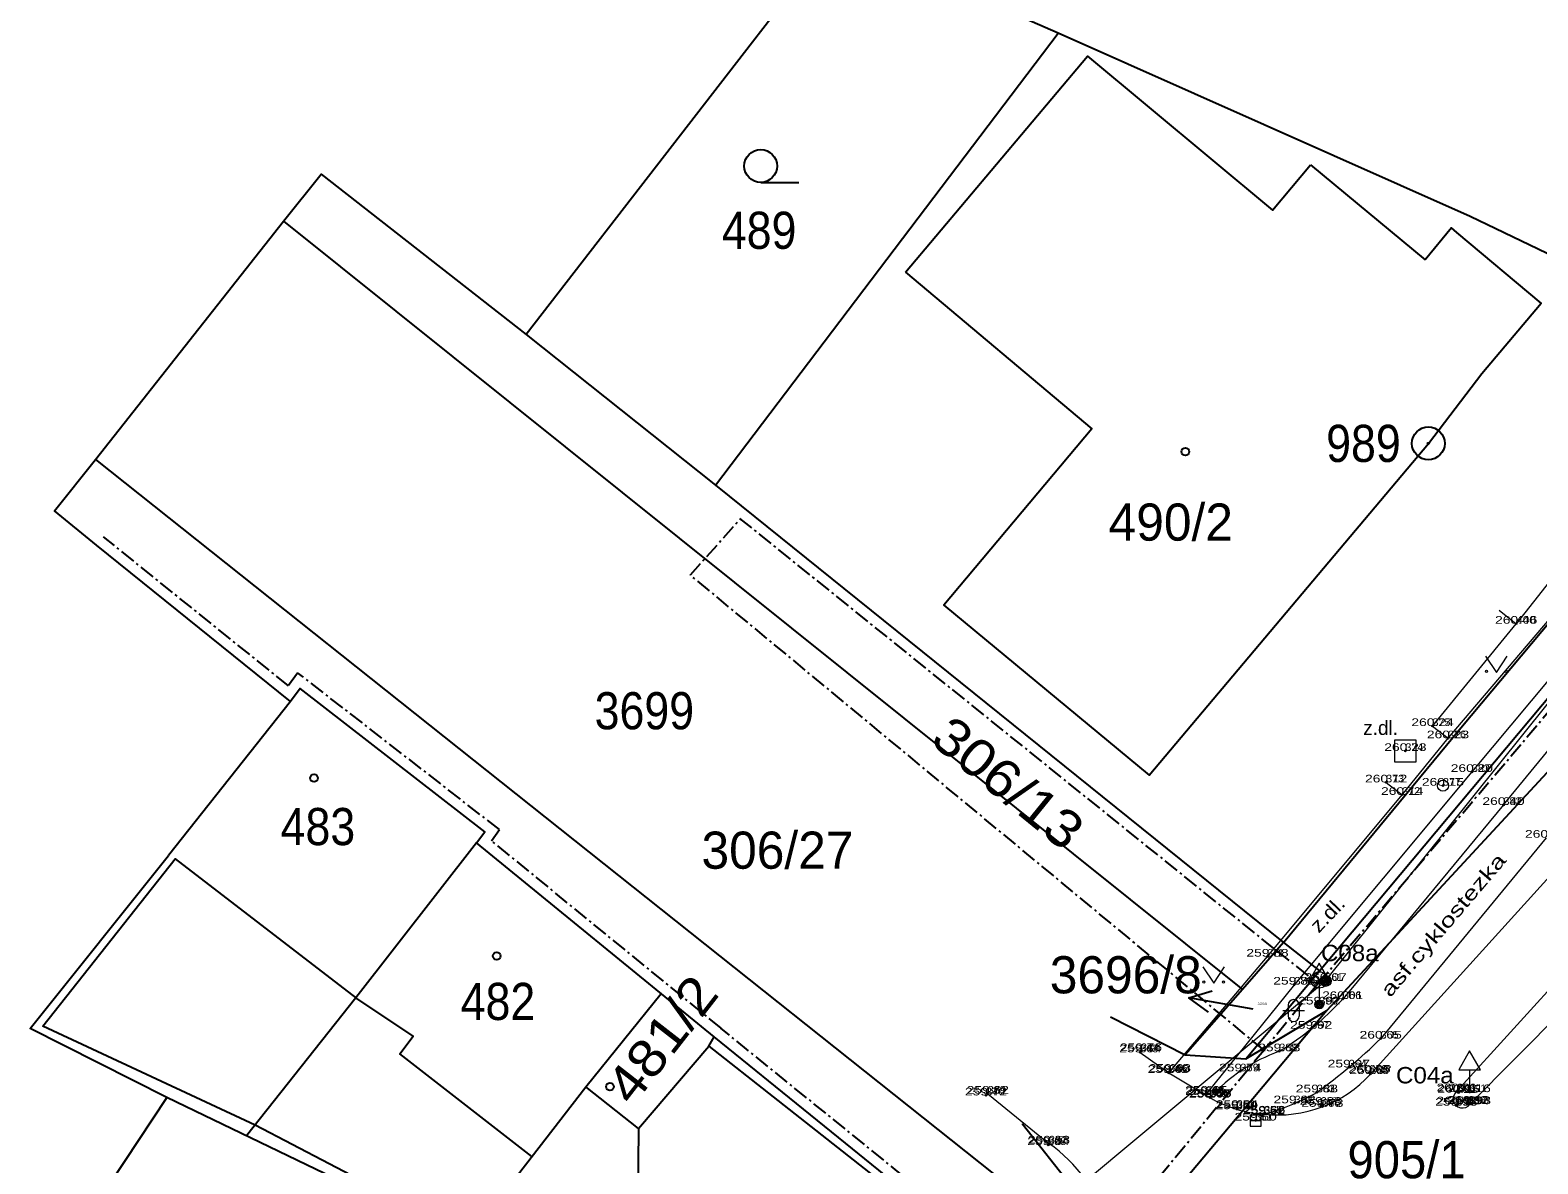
# Model space of a CAD drawing. Extents: x -568530 to -568223, y -1154101 to -1153740.
# Drawn here: x -568529.8 to -568460.8, y -1153988.4 to -1153936.5 of the extents above; entities that cross this region are included whole.
import ezdxf
from ezdxf.enums import TextEntityAlignment as Align

# ---------------------------------------------------------------- set-up
doc = ezdxf.new("R2010")
doc.units = 0
doc.header["$LTSCALE"] = 0.14
doc.header["$PDMODE"] = 32
doc.header["$PDSIZE"] = 0.07
doc.linetypes.add('DOT_DASHED', pattern=[7.7, 5, -1.2, 0.3, -1.2])
for name, color, linetype, lineweight in [('1', 7, 'Continuous', 25), ('10', 7, 'Continuous', 13), ('11', 7, 'Continuous', 13), ('12', 7, 'Continuous', 13), ('17', 7, 'Continuous', 13), ('25', 7, 'Continuous', 13), ('26', 7, 'Continuous', 13), ('27', 7, 'Continuous', 13), ('28', 7, 'Continuous', 13), ('33', 7, 'Continuous', 13), ('34', 7, 'Continuous', 13), ('36', 7, 'Continuous', 13), ('4', 7, 'Continuous', 25), ('42', 7, 'Continuous', 13), ('51', 7, 'Continuous', 13), ('6', 7, 'DOT_DASHED', 25), ('7', 7, 'Continuous', 13)]:
    doc.layers.add(name, color=color, linetype=linetype, lineweight=lineweight)
for name, color, linetype in [('13', 7, 'Continuous'), ('18', 7, 'Continuous'), ('19', 7, 'Continuous'), ('20', 7, 'Continuous'), ('40', 7, 'Continuous')]:
    doc.layers.add(name, color=color, linetype=linetype)

msp = doc.modelspace()

# ---------------------------------------------------------------- linework, layer by layer
at = {"layer": '1'}
for p, q in [((-568463.93, -1153945.07), (-568482.79, -1153936.68)), ((-568471.25, -1153942.71), (-568466, -1153947.05)), ((-568450.23, -1153951.69), (-568463.93, -1153945.07)), ((-568517.91, -1153967.26), (-568523.5, -1153974.31)), ((-568472.48, -1153978.28), (-568470.83, -1153979.58))]:
    msp.add_line(p, q, dxfattribs=at)
for points in [[(-568474.2, -1153983.6), (-568452.46, -1153957.65), (-568449.01, -1153953.16), (-568441.85, -1153945.56), (-568434.01, -1153937.23), (-568430.2, -1153935.69), (-568428.09, -1153933.47), (-568426.88, -1153931.62), (-568414.57, -1153911.32), (-568413.31, -1153909.52)], [(-568421.22, -1153939.56), (-568428.14, -1153935.17), (-568430.26, -1153937.4), (-568443.63, -1153952.29), (-568447.7, -1153956.78), (-568470.49, -1153981.39)], [(-568489.78, -1153947.62), (-568481.45, -1153937.73), (-568472.98, -1153944.78), (-568471.25, -1153942.71)], [(-568526.84, -1153956.18), (-568518.24, -1153945.29), (-568516.51, -1153943.13), (-568507.14, -1153950.47)], [(-568465.85, -1153955.45), (-568463.4, -1153952.25), (-568460.68, -1153949.03), (-568464.54, -1153945.8), (-568464.79, -1153945.59), (-568466, -1153947.05)], [(-568489.78, -1153947.62), (-568481.25, -1153954.78), (-568488.02, -1153962.85), (-568478.62, -1153970.63), (-568465.85, -1153955.45)], [(-568498.47, -1153957.36), (-568472.48, -1153978.28), (-568467.49, -1153972.24), (-568464.36, -1153968.47), (-568450.95, -1153952.46)], [(-568483.3, -1153990.8), (-568485.31, -1153993.31), (-568498.53, -1153982.6), (-568509.4, -1153973.73), (-568509.03, -1153973.22), (-568517.48, -1153966.66), (-568517.91, -1153967.26), (-568526.79, -1153960.11), (-568528.72, -1153958.54), (-568526.84, -1153956.18)], [(-568509.4, -1153973.73), (-568514.92, -1153980.82), (-568519.93, -1153987.13)], [(-568523.58, -1153985.37), (-568529.83, -1153982.22), (-568523.5, -1153974.31)], [(-568472.48, -1153978.28), (-568474.36, -1153980.44), (-568476.98, -1153983.42), (-568474.2, -1153983.6), (-568470.49, -1153981.39)], [(-568501.99, -1153986.8), (-568504.41, -1153984.88), (-568500.96, -1153980.62)], [(-568470.49, -1153981.39), (-568474.36, -1153986), (-568480.23, -1153992.99), (-568483.12, -1153996.42), (-568489.9, -1154005.63), (-568508.72, -1154028.73)], [(-568501.99, -1153986.8), (-568498.78, -1153983.02), (-568498.53, -1153982.6)], [(-568502.03, -1153990.93), (-568508.67, -1153990.41), (-568504.41, -1153984.88)], [(-568508.67, -1153990.41), (-568510.29, -1153992.32), (-568515.06, -1153989.47), (-568523.58, -1153985.37), (-568528.1, -1153992.22), (-568521.58, -1153995.13), (-568500.56, -1154012.05), (-568494.94, -1154005.21), (-568491.05, -1154000.52)]]:
    msp.add_lwpolyline(points, dxfattribs=at)
msp.add_lwpolyline([(-568498.47, -1153957.36), (-568482.79, -1153936.68), (-568493.01, -1153932.21), (-568507.14, -1153950.47)], close=True, dxfattribs=at)
at = {"layer": '10'}
for p, q in [((-568468.5, -1153984.3), (-568459.56, -1153974.44)), ((-568464.54, -1153985.09), (-568457.22, -1153977.01)), ((-568486.01, -1153985.2), (-568483.21, -1153987.48))]:
    msp.add_line(p, q, dxfattribs=at)
for points in [[(-568463.95, -1153985.68), (-568459.72, -1153981.43), (-568456.47, -1153977.68)], [(-568479.03, -1153983.31), (-568477.73, -1153984.25), (-568476.04, -1153985.26), (-568475.84, -1153985.38)]]:
    msp.add_lwpolyline(points, dxfattribs=at)
for centre, radius, start, end in [((-568472.7383, -1153980.4472), 5.7278, 263.66789, 317.72758), ((-568472.9663, -1153980.4342), 5.7201, 239.84169, 265.95285), ((-568464.292, -1153985.432), 0.4224, 125.95584, 324.04416), ((-568487.1888, -1153993.1519), 6.9283, 16.6224, 54.95079)]:
    msp.add_arc(centre, radius, start, end, dxfattribs=at)
at = {"layer": '11'}
for p, q in [((-568465.66, -1153968.38), (-568461.83, -1153963.7)), ((-568465.66, -1153968.38), (-568464.95, -1153968.94)), ((-568463.86, -1153970.48), (-568471.98, -1153980.21)), ((-568467.78, -1153970.96), (-568467.05, -1153971.53)), ((-568462.41, -1153971.99), (-568469.77, -1153980.87)), ((-568460.46, -1153973.49), (-568468.03, -1153982.68)), ((-568477.73, -1153984.25), (-568473.21, -1153978.93)), ((-568471.98, -1153980.21), (-568476.04, -1153985.26))]:
    msp.add_line(p, q, dxfattribs=at)
for points in [[(-568442.59, -1153945.91), (-568443.65, -1153947.05), (-568450.12, -1153954.09), (-568450.55, -1153954.6), (-568457.5, -1153962.87), (-568463.86, -1153970.48)], [(-568462.41, -1153971.99), (-568455.94, -1153964.12), (-568449.09, -1153955.83), (-568442.48, -1153947.86)], [(-568464.95, -1153968.94), (-568458.91, -1153961.84), (-568451.46, -1153952.92)], [(-568473.21, -1153978.93), (-568467.05, -1153971.53), (-568464.95, -1153968.94)]]:
    msp.add_lwpolyline(points, dxfattribs=at)
for centre, radius, start, end in [((-568479.5527, -1153971.9543), 13.236, 301.33199, 317.65447), ((-568486.5097, -1153963.7078), 26.4848, 305.97945, 314.24653), ((-568469.9419, -1153990.7693), 7.9896, 109.96597, 137.58085), ((-568476.5758, -1153974.9538), 11.6365, 285.99146, 298.91164)]:
    msp.add_arc(centre, radius, start, end, dxfattribs=at)
for p in [(-568461.83, -1153963.7), (-568465.66, -1153968.38), (-568464.95, -1153968.94), (-568466.9, -1153969.52), (-568463.86, -1153970.48), (-568467.78, -1153970.96), (-568465.18, -1153971.11), (-568467.05, -1153971.53), (-568462.41, -1153971.99), (-568473.21, -1153978.93), (-568470.55, -1153980.04), (-568471.98, -1153980.21), (-568470.84, -1153981.12), (-568469.77, -1153980.87), (-568471.21, -1153982.23), (-568468.03, -1153982.68), (-568479.03, -1153983.31), (-568479, -1153983.25), (-568472.67, -1153983.26), (-568477.73, -1153984.25), (-568477.68, -1153984.2), (-568474.46, -1153984.18), (-568469.49, -1153984), (-568468.54, -1153984.24), (-568468.5, -1153984.3), (-568486.09, -1153985.28), (-568486.01, -1153985.2), (-568476.04, -1153985.26), (-568476.01, -1153985.2), (-568475.84, -1153985.38), (-568475.82, -1153985.35), (-568471.97, -1153985.64), (-568470.95, -1153985.14), (-568464.54, -1153985.09), (-568464.47, -1153985.15), (-568464.02, -1153985.66), (-568463.96, -1153985.13), (-568474.62, -1153985.91), (-568474.61, -1153985.85), (-568473.37, -1153986.14), (-568473.36, -1153986.11), (-568470.77, -1153985.71), (-568470.7, -1153985.8), (-568464.57, -1153985.75), (-568464.51, -1153985.69), (-568463.95, -1153985.68), (-568473.75, -1153986.43), (-568483.24, -1153987.55), (-568483.21, -1153987.48)]:
    msp.add_point(p, dxfattribs=at)
at = {"layer": '25', "lineweight": 25}
for p, q in [((-568496.4, -1153943.51), (-568494.65, -1153943.51)), ((-568473.86, -1153981.34), (-568476.812, -1153980.809))]:
    msp.add_line(p, q, dxfattribs=at)
msp.add_lwpolyline([(-568475.916, -1153981.477), (-568476.812, -1153980.809), (-568475.739, -1153980.494)], dxfattribs=at)
for centre, radius in [((-568496.4, -1153942.76), 0.75), ((-568465.85, -1153955.45), 0.75), ((-568476.97, -1153955.83), 0.175), ((-568465.85, -1153955.45), 0.032), ((-568516.84, -1153970.76), 0.175), ((-568508.48, -1153978.9), 0.175), ((-568503.3, -1153984.88), 0.175)]:
    msp.add_circle(centre, radius, dxfattribs=at)
at = {"layer": '25'}
for radius in [0.25, 0.2, 0.15, 0.1, 0.05]:
    msp.add_circle((-568470.55, -1153980.04), radius, dxfattribs=at)
at = {"layer": '26'}
msp.add_lwpolyline([(-568467.4, -1153970.02), (-568466.4, -1153970.02), (-568466.4, -1153969.02), (-568467.4, -1153969.02)], close=True, dxfattribs=at)
at = {"layer": '27'}
msp.add_line((-568474, -1153986.43), (-568473.5, -1153986.43), dxfattribs=at)
msp.add_lwpolyline([(-568474, -1153986.68), (-568473.5, -1153986.68), (-568473.5, -1153986.18), (-568474, -1153986.18)], close=True, dxfattribs=at)
at = {"layer": '28'}
msp.add_circle((-568465.18, -1153971.11), 0.25, dxfattribs=at)
at = {"layer": '33'}
for p, q in [((-568471.105, -1153980.26), (-568470.575, -1153979.73)), ((-568471.105, -1153979.73), (-568470.575, -1153980.26)), ((-568470.84, -1153980.37), (-568470.84, -1153981.12))]:
    msp.add_line(p, q, dxfattribs=at)
for centre, radius in [((-568470.84, -1153979.995), 0.375), ((-568470.84, -1153981.12), 0.2), ((-568470.84, -1153981.12), 0.1445), ((-568470.84, -1153981.12), 0.0876)]:
    msp.add_circle(centre, radius, dxfattribs=at)
at = {"layer": '34'}
for p, q in [((-568470.84, -1153980.102), (-568470.84, -1153981.12)), ((-568463.96, -1153984.112), (-568463.96, -1153985.13)), ((-568464.21, -1153985.13), (-568463.71, -1153985.13))]:
    msp.add_line(p, q, dxfattribs=at)
for points in [[(-568471.34, -1153980.102), (-568470.34, -1153980.102), (-568470.84, -1153979.236)], [(-568464.46, -1153984.112), (-568463.46, -1153984.112), (-568463.96, -1153983.246)]]:
    msp.add_lwpolyline(points, close=True, dxfattribs=at)
at = {"layer": '36'}
for p, q in [((-568472.514, -1153981.398), (-568471.514, -1153981.398)), ((-568472.264, -1153981.148), (-568472.264, -1153981.648)), ((-568471.764, -1153981.148), (-568471.764, -1153981.648))]:
    msp.add_line(p, q, dxfattribs=at)
for points in [[(-568463.237, -1153965.178), (-568462.737, -1153965.928), (-568462.237, -1153965.178)], [(-568476.172, -1153979.393), (-568475.672, -1153980.143), (-568475.172, -1153979.393)]]:
    msp.add_lwpolyline(points, dxfattribs=at)
for centre in [(-568463.1878, -1153965.8784), (-568462.2884, -1153965.8784), (-568476.1232, -1153980.0934), (-568475.2238, -1153980.0934)]:
    msp.add_circle(centre, 0.05, dxfattribs=at)
for centre, start, end in [((-568472.0136, -1153981.1489), 0, 180), ((-568472.0136, -1153981.6489), 180, 0)]:
    msp.add_arc(centre, 0.25, start, end, dxfattribs=at)
at = {"layer": '4'}
for p, q in [((-568518.24, -1153945.29), (-568474.36, -1153980.44)), ((-568526.84, -1153956.18), (-568483.3, -1153990.8)), ((-568480.4, -1153981.68), (-568476.98, -1153983.42)), ((-568498.78, -1153983.02), (-568485.47, -1153993.49)), ((-568501.99, -1153986.8), (-568502.03, -1153990.93)), ((-568484.44, -1153986.56), (-568482.11, -1153989.53))]:
    msp.add_line(p, q, dxfattribs=at)
for points in [[(-568509.95, -1153991.92), (-568514.46, -1153989.29), (-568519.54, -1153986.64), (-568529.25, -1153982.11), (-568523.19, -1153974.46), (-568514.92, -1153980.82)], [(-568506.87, -1153988.07), (-568512.92, -1153983.38), (-568512.3, -1153982.57), (-568514.92, -1153980.82)]]:
    msp.add_lwpolyline(points, dxfattribs=at)
at = {"layer": '51'}
msp.add_lwpolyline([(-568486.26, -1153993.13), (-568470.55, -1153980.04), (-568452.49, -1153957.53), (-568437.543, -1153968.589)], dxfattribs=at)
at = {"layer": '6'}
for p, q in [((-568470.89, -1153980.16), (-568452.08, -1153957.97)), ((-568499.62, -1153961.47), (-568497.34, -1153958.91)), ((-568497.37, -1153958.88), (-568472.79, -1153978.67)), ((-568518.01, -1153966.54), (-568526.48, -1153959.72)), ((-568473.37, -1153983.21), (-568499.62, -1153961.47)), ((-568517.6, -1153965.96), (-568518.01, -1153966.54)), ((-568508.35, -1153973.12), (-568517.59, -1153965.94)), ((-568508.72, -1153973.63), (-568508.35, -1153973.12)), ((-568498.21, -1153982.21), (-568508.72, -1153973.63)), ((-568472.79, -1153978.67), (-568470.89, -1153980.16)), ((-568482.83, -1153994.68), (-568498.22, -1153982.21))]:
    msp.add_line(p, q, dxfattribs=at)
msp.add_lwpolyline([(-568470.91, -1153980.18), (-568473.37, -1153983.21), (-568482.77, -1153994.61)], dxfattribs=at)
at = {"layer": '7'}
msp.add_line((-568462.615, -1153963.08), (-568461.83, -1153963.7), dxfattribs=at)
msp.add_lwpolyline([(-568450.39, -1153949.74), (-568453.8, -1153950.8), (-568454.03, -1153954.12), (-568459.68, -1153960.98), (-568461.83, -1153963.7)], dxfattribs=at)

# ---------------------------------------------------------------- texts
at = {"layer": '12'}
for s, width, p in [('260.46', 1.35, (-568461.83, -1153963.7)), ('260.24', 1.35, (-568465.66, -1153968.38)), ('260.23', 1.35, (-568464.95, -1153968.94)), ('260.23', 1.35, (-568466.9, -1153969.52)), ('260.20', 1.35, (-568463.8595, -1153970.48)), ('260.12', 1.35, (-568467.78, -1153970.96)), ('260.15', 1.35, (-568465.1805, -1153971.11)), ('260.14', 1.35, (-568467.05, -1153971.53)), ('260.40', 1.35, (-568462.4095, -1153971.99)), ('260.44', 1.35, (-568460.46, -1153973.49)), ('259.88', 1.35, (-568473.21, -1153978.93)), ('259.85', 1.35, (-568471.9805, -1153980.21)), ('260.07', 1.35, (-568470.55, -1153980.04)), ('259.92', 1.35, (-568470.84, -1153981.12)), ('260.01', 1.3, (-568469.77, -1153980.87)), ('259.92', 1.35, (-568471.21, -1153982.23)), ('260.05', 1.35, (-568468.0305, -1153982.68)), ('259.64', 1.35, (-568479.03, -1153983.31)), ('259.76', 1.35, (-568479, -1153983.25)), ('259.83', 1.35, (-568472.67, -1153983.26)), ('259.60', 1.35, (-568477.7295, -1153984.25)), ('259.63', 1.35, (-568477.68, -1153984.2)), ('259.74', 1.35, (-568474.46, -1153984.18)), ('259.97', 1.35, (-568469.49, -1153984)), ('260.05', 1.35, (-568468.5405, -1153984.24)), ('259.87', 1.35, (-568468.5, -1153984.3)), ('259.72', 1.35, (-568486.09, -1153985.28)), ('259.62', 1.35, (-568486.01, -1153985.2)), ('259.65', 1.35, (-568476.0105, -1153985.2)), ('259.61', 1.3, (-568476.04, -1153985.26)), ('259.88', 1.35, (-568470.95, -1153985.14)), ('260.01', 1.3, (-568464.54, -1153985.09)), ('260.15', 1.35, (-568464.4705, -1153985.15)), ('260.16', 1.35, (-568463.96, -1153985.13)), ('259.60', 1.35, (-568475.8395, -1153985.38)), ('259.65', 1.35, (-568475.8205, -1153985.35)), ('259.60', 1.35, (-568474.6195, -1153985.91)), ('259.64', 1.35, (-568474.61, -1153985.85)), ('259.82', 1.35, (-568471.97, -1153985.64)), ('259.88', 1.35, (-568470.77, -1153985.71)), ('259.73', 1.35, (-568470.7, -1153985.8)), ('259.98', 1.35, (-568464.57, -1153985.75)), ('260.12', 1.35, (-568464.51, -1153985.69)), ('260.13', 1.35, (-568464.02, -1153985.66)), ('259.98', 1.35, (-568463.95, -1153985.68)), ('259.60', 1.35, (-568473.7495, -1153986.43)), ('259.62', 1.35, (-568473.37, -1153986.14)), ('259.66', 1.35, (-568473.36, -1153986.11)), ('259.64', 1.35, (-568483.24, -1153987.55)), ('259.53', 1.35, (-568483.21, -1153987.48))]:
    msp.add_text(s, height=0.35, dxfattribs=dict(at, width=width)).set_placement(p, align=Align.CENTER)
at = {"layer": '13'}
for s, width, p in [('400', 1.15, (-568461.83, -1153963.7)), ('375', 1.05, (-568465.66, -1153968.38)), ('376', 1.05, (-568464.95, -1153968.94)), ('374', 1.05, (-568466.9, -1153969.52)), ('383', 1.05, (-568463.86, -1153970.48)), ('373', 1.05, (-568467.78, -1153970.96)), ('377', 1.05, (-568465.18, -1153971.11)), ('372', 1.05, (-568467.05, -1153971.53)), ('382', 1.05, (-568462.41, -1153971.99)), ('371', 0.95, (-568473.21, -1153978.93)), ('370', 1.1, (-568471.98, -1153980.21)), ('360', 1.1, (-568470.84, -1153981.12)), ('366', 1.1, (-568469.77, -1153980.87)), ('367', 1.05, (-568471.21, -1153982.23)), ('365', 1.05, (-568468.03, -1153982.68)), ('343', 1.05, (-568479.03, -1153983.31)), ('344', 1.05, (-568479, -1153983.25)), ('368', 1.05, (-568472.67, -1153983.26)), ('345', 1.05, (-568477.73, -1153984.25)), ('346', 1.05, (-568477.68, -1153984.2)), ('369', 1.1, (-568474.46, -1153984.18)), ('364', 1.05, (-568469.49, -1153984)), ('359', 1.05, (-568468.54, -1153984.24)), ('358', 1.05, (-568468.5, -1153984.3)), ('340', 1.1, (-568486.09, -1153985.28)), ('339', 1.05, (-568486.01, -1153985.2)), ('347', 1.05, (-568476.04, -1153985.26)), ('348', 1.05, (-568476.01, -1153985.2)), ('363', 1.05, (-568470.95, -1153985.14)), ('396', 1.1, (-568464.54, -1153985.09)), ('397', 1.05, (-568464.47, -1153985.15)), ('391', 0.95, (-568463.96, -1153985.13)), ('349', 1.05, (-568475.84, -1153985.38)), ('350', 1.1, (-568475.82, -1153985.35)), ('352', 1.05, (-568474.62, -1153985.91)), ('353', 1.05, (-568474.61, -1153985.85)), ('362', 1.05, (-568471.97, -1153985.64)), ('357', 1.05, (-568470.77, -1153985.71)), ('356', 1.05, (-568470.7, -1153985.8)), ('394', 1.05, (-568464.57, -1153985.75)), ('395', 1.05, (-568464.51, -1153985.69)), ('393', 1.05, (-568464.02, -1153985.66)), ('392', 1.05, (-568463.95, -1153985.68)), ('351', 0.95, (-568473.75, -1153986.43)), ('354', 1.05, (-568473.37, -1153986.14)), ('355', 1.05, (-568473.36, -1153986.11)), ('338', 1.05, (-568483.24, -1153987.55)), ('337', 1.05, (-568483.21, -1153987.48))]:
    msp.add_text(s, height=0.35, dxfattribs=dict(at, width=width)).set_placement(p)
msp.add_text('361', height=0.35, dxfattribs=at).set_placement((-568470.55, -1153980.04))
at = {"layer": '17', "width": 0.9}
msp.add_text('989', height=1.7, dxfattribs=at).set_placement((-568467.113, -1153956.3), align=Align.RIGHT)
at = {"layer": '18', "width": 0.9}
for s, p in [('489', (-568498.18, -1153946.55)), ('3699', (-568504, -1153968.53))]:
    msp.add_text(s, height=1.7, dxfattribs=at).set_placement(p)
at = {"layer": '18'}
msp.add_text('3696/8', height=1.7, dxfattribs=at).set_placement((-568476.219, -1153980.61), align=Align.RIGHT)
msp.add_text('3696/8', height=0.1, dxfattribs=at).set_placement((-568473.66, -1153981.14))
at = {"layer": '19'}
msp.add_text('490/2', height=1.7, dxfattribs=at).set_placement((-568480.48, -1153959.9))
at = {"layer": '19', "width": 0.9}
for s, p in [('483', (-568518.37, -1153973.83)), ('482', (-568510.13, -1153981.83))]:
    msp.add_text(s, height=1.7, dxfattribs=at).set_placement(p)
at = {"layer": '19', "width": 1.15}
msp.add_text('481/2', height=1.7, rotation=52.1, dxfattribs=at).set_placement((-568502.264, -1153985.82))
at = {"layer": '20', "width": 1.15}
msp.add_text('306/13', height=1.7, rotation=320.903, dxfattribs=at).set_placement((-568488.709, -1153969.121))
at = {"layer": '20'}
msp.add_text('306/27', height=1.7, dxfattribs=at).set_placement((-568499.11, -1153974.91))
at = {"layer": '20', "width": 0.95}
msp.add_text('905/1', height=1.7, dxfattribs=at).set_placement((-568469.55, -1153989.07))
at = {"layer": '40'}
msp.add_text('z.dl.', height=0.65, dxfattribs=at).set_placement((-568468.831, -1153968.788))
for s, rotation, width, p in [('asf.cyklostezka', 49.573, 1.4, (-568467.598, -1153980.833)), ('z.dl.', 46.41, 1.15, (-568470.865, -1153977.883))]:
    msp.add_text(s, height=0.65, rotation=rotation, dxfattribs=dict(at, width=width)).set_placement(p)
at = {"layer": '42', "width": 1.1}
for s, p in [('C08a', (-568469.4445, -1153979.138)), ('C04a', (-568466.0105, -1153984.73))]:
    msp.add_text(s, height=0.75, dxfattribs=at).set_placement(p, align=Align.CENTER)

doc.saveas('drawing.dxf')
